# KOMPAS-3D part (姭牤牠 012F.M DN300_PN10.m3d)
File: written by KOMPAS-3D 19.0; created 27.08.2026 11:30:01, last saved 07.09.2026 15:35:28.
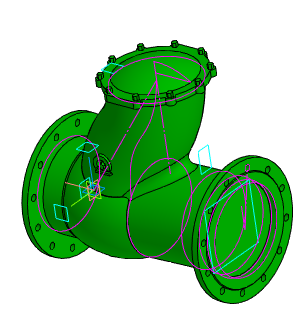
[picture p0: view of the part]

Document properties: Автор: Энергия; Полное имя файла: Z:\3.Личные\kachalov\001_3d для проектировщиков\х.х Тип 012F\012F.M\Клапан 012F.M DN300_PN10.m3d

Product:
- Part/product: (unnamed)  | designation Клапан 012F.M DN300_PN10
    Масса: 304.264

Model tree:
1. Эскиз:1
2. Элемент вращения:1
     Угол 1 = 360
3. Эскиз:2  (with: Элемент вращения:1)
4. Параллельная плоскость:3
5. Эскиз:26
6. Смещенная плоскость:5
     Расстояние = 150
7. Элемент по траектории:1
     Толщина стенки 1 = 1
8. Эскиз:31
9. Эскиз:38  (with: Элемент вращения:1)
10. Параллельная плоскость:4
11. Смещенная плоскость:2  (with: Элемент вращения:1)
     Расстояние = 32
12. Эскиз:39  (with: Элемент вращения:1)
13. Эскиз:40  (with: Элемент вращения:1)
14. Смещенная плоскость:3
     Расстояние = 33
15. Эскиз:42  (with: Элемент вращения:1)
16. Элемент по сечениям:4
17. Элемент вращения:6  (with: Элемент вращения:1)
     Угол 1 = 360
18. Эскиз:10  (with: Элемент вращения:1)
19. Элемент выдавливания:3  (with: Элемент вращения:1)
     Расстояние 2 = 22
20. Массив по концентрической сетке:1  (with: Элемент выдавливания:3, Эскиз:10, Элемент вращения:1)  (12 pattern instances)
     Шаг 2 = 360
21. Эскиз:11  (with: Элемент вращения:1)
22. Элемент выдавливания:4  (with: Элемент вращения:1)
23. Массив по концентрической сетке:2  (with: Элемент выдавливания:4, Эскиз:11, Элемент вращения:1)  (12 pattern instances)
     Шаг 2 = 360
24. Эскиз:32
25. Элемент выдавливания:13
     Расстояние 1 = 25
26. Эскиз:33  (with: Элемент выдавливания:13)
27. Элемент вращения:7
     Угол 1 = 360
28. Эскиз:34  (with: Элемент вращения:1, Элемент вращения:6)
29. Элемент выдавливания:14  (with: Элемент вращения:6)
     Расстояние 1 = 190; Смещение 1 = 10
30. Скругление:23  (with: Элемент выдавливания:14)
     Радиус = 3
31. Эскиз:35  (with: Элемент выдавливания:14)
32. Элемент выдавливания:15
     Расстояние 1 = 10
33. Эскиз:36  (with: Элемент выдавливания:13)
34. Элемент выдавливания:16
     Расстояние 1 = 15
35. Эскиз:43  (with: Элемент выдавливания:13)
36. Массив по концентрической сетке:3  (with: Элемент выдавливания:16, Эскиз:36, Эскиз:33)  (10 pattern instances)
     Шаг 2 = 360
37. Смещенная плоскость:4
     Расстояние = 160
38. Эскиз:46
39. Элемент выдавливания:20  (with: Элемент по траектории:1)
     Расстояние 2 = 9.21632
40. Эскиз:47  (with: Элемент вращения:1)
41. Эскиз:48  (with: Элемент вращения:1)
42. Элемент выдавливания:22
     Расстояние 2 = 360
43. Эскиз:49  (with: Элемент вращения:1)
44. Скругление:28  (with: Элемент по сечениям:4)
     Радиус = 30
45. Скругление:29  (with: Элемент вращения:6)
     Радиус = 20

Expressions: Dn/2; D/2; D2/2; 360/(2*n); 360/(n*2); D3/2
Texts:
  Клапан 012F.M DN300_PN10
